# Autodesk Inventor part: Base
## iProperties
Shininess: 77.0
Length Units: 11269
Angle Units: 11279
Time Units: 11290
Mass Units: 11283
Length Display Precision: 3
Angle Display Precision: 2
Created: 2002-02
Part Number: Base
Document SubType Name: Modeling
Designer: ***
Density: 1 g/cm^3
Density: 0.0
Volumn: 0.0
Area: 0.0
PropertySet Name: Model Information
Control State: 0
Master: False
Checked Out: False
Author: ***
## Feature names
1. Extrusion1
2. Extrusion3
3. Extrusion4
4. Hole1
5. Rectangular Pattern1
6. Hole2
7. Rectangular Pattern2
